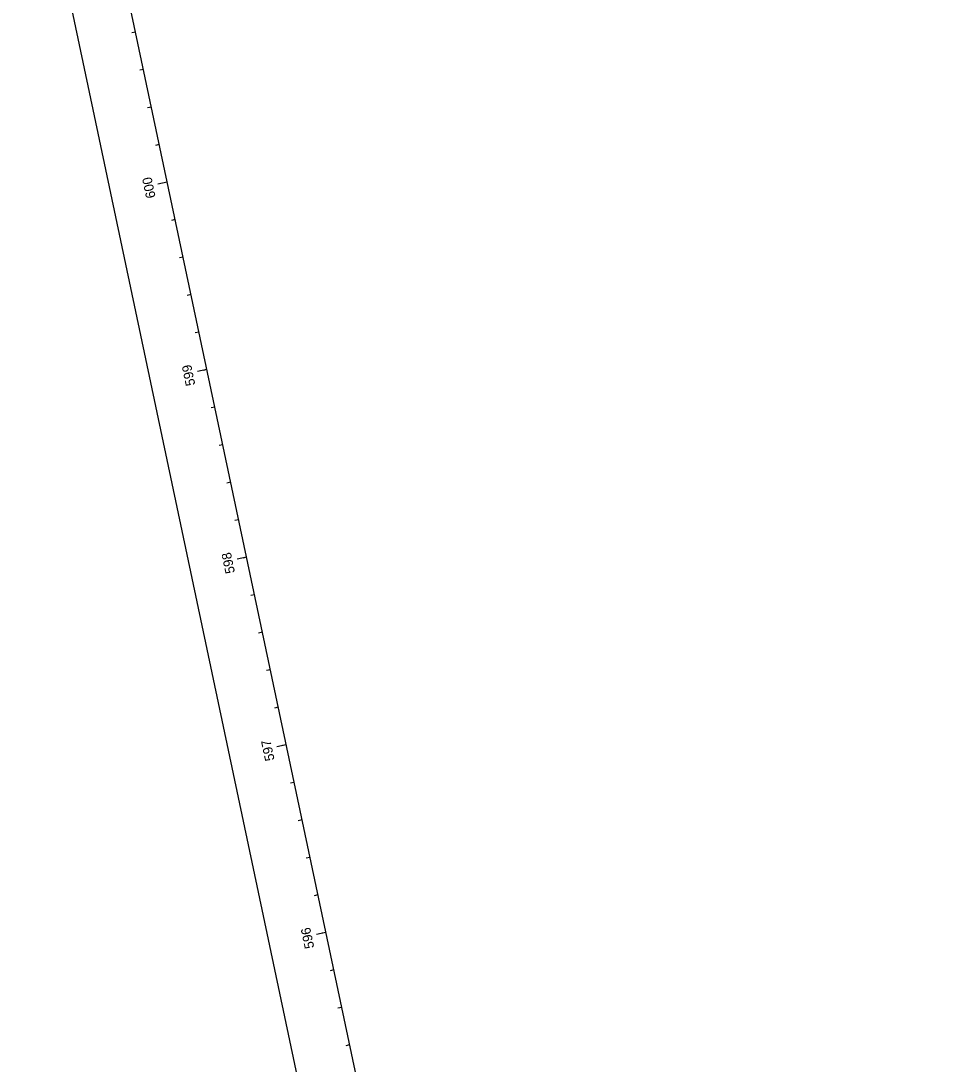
# Model space of a CAD drawing. Extents: x 2003883 to 2007688, y 399149 to 412300.
# Drawn here: x 2005065 to 2005555, y 406834 to 407378 of the extents above; entities that cross this region are included whole.
import ezdxf

# ---------------------------------------------------------------- set-up
doc = ezdxf.new("R2010")
doc.units = 0
for name, color, linetype in [('BaselineSurvey', 7, 'Continuous'), ('BaselineTextWt2', 7, 'Continuous'), ('DataBoxWt2', 7, 'Continuous'), ('Default', 7, 'Continuous'), ('EaseLine_ep', 7, 'Continuous'), ('PropertyLine_ep', 7, 'Continuous'), ('PropertyLineHook_ep', 7, 'Continuous'), ('PropertyLineSymbol_ep', 7, 'Continuous'), ('SubDivLineText', 7, 'Continuous'), ('SubLotNumberText', 7, 'Continuous'), ('SubVacOrigLotStaTie', 7, 'Continuous')]:
    doc.layers.add(name, color=color, linetype=linetype)

msp = doc.modelspace()

# ---------------------------------------------------------------- linework, layer by layer
at = {"layer": 'DataBoxWt2'}
for p, q in [((2005141.48, 407293.74), (2005136.59, 407292.71)), ((2005182.86, 407098.07), (2005180.9, 407097.66)), ((2005224.23, 406902.4), (2005222.27, 406901.98))]:
    msp.add_line(p, q, dxfattribs=at)
at = {"layer": 'Default'}
msp.add_line((2006223.92, 402174.38), (2005094.48, 407516.05), dxfattribs=at)
at = {"layer": 'EaseLine_ep'}
msp.add_line((2006194.57, 402168.18), (2005065.13, 407509.84), dxfattribs=at)
at = {"layer": 'PropertyLine_ep'}
msp.add_line((2006223.92, 402174.38), (2005094.48, 407516.05), dxfattribs=at)
at = {"layer": 'PropertyLineHook_ep'}
for p, q in [((2005124.93, 407372.01), (2005122.98, 407371.6)), ((2005129.07, 407352.45), (2005127.11, 407352.03)), ((2005133.21, 407332.88), (2005131.25, 407332.46)), ((2005137.35, 407313.31), (2005135.39, 407312.9)), ((2005141.48, 407293.74), (2005136.59, 407292.71)), ((2005145.62, 407274.18), (2005143.66, 407273.76)), ((2005149.76, 407254.61), (2005147.8, 407254.2)), ((2005153.89, 407235.04), (2005151.94, 407234.63)), ((2005158.03, 407215.47), (2005156.08, 407215.06)), ((2005162.17, 407195.91), (2005157.28, 407194.87)), ((2005166.31, 407176.34), (2005164.35, 407175.93)), ((2005170.44, 407156.77), (2005168.49, 407156.36)), ((2005174.58, 407137.2), (2005172.62, 407136.79)), ((2005178.72, 407117.64), (2005176.76, 407117.22)), ((2005182.86, 407098.07), (2005177.96, 407097.04)), ((2005186.99, 407078.5), (2005185.04, 407078.09)), ((2005191.13, 407058.93), (2005189.17, 407058.52)), ((2005195.27, 407039.37), (2005193.31, 407038.95)), ((2005199.41, 407019.8), (2005197.45, 407019.39)), ((2005203.54, 407000.23), (2005198.65, 406999.2)), ((2005207.68, 406980.67), (2005205.72, 406980.25)), ((2005211.82, 406961.1), (2005209.86, 406960.68)), ((2005215.95, 406941.53), (2005214, 406941.12)), ((2005220.09, 406921.96), (2005218.14, 406921.55)), ((2005224.23, 406902.4), (2005219.34, 406901.36)), ((2005228.37, 406882.83), (2005226.41, 406882.41)), ((2005232.5, 406863.26), (2005230.55, 406862.85)), ((2005236.64, 406843.69), (2005234.68, 406843.28))]:
    msp.add_line(p, q, dxfattribs=at)
at = {"layer": 'SubDivLineText'}
for p, q in [((2005141.48, 407293.74), (2005136.59, 407292.71)), ((2005162.17, 407195.91), (2005160.21, 407195.49)), ((2005182.86, 407098.07), (2005180.9, 407097.66)), ((2005203.54, 407000.23), (2005201.59, 406999.82)), ((2005224.23, 406902.4), (2005222.27, 406901.98))]:
    msp.add_line(p, q, dxfattribs=at)
at = {"layer": 'SubVacOrigLotStaTie'}
msp.add_line((2005141.48, 407293.74), (2005136.59, 407292.71), dxfattribs=at)

# ---------------------------------------------------------------- texts
at = {"layer": 'BaselineSurvey'}
msp.add_text('600', height=4.98, rotation=101.9388, dxfattribs=at).set_placement((2005135.49, 407285.84))
at = {"layer": 'BaselineTextWt2'}
msp.add_text('600', height=4.98, rotation=101.9388, dxfattribs=at).set_placement((2005135.49, 407285.84))
at = {"layer": 'PropertyLineSymbol_ep'}
for s, p in [('600', (2005135.49, 407285.84)), ('599', (2005156.18, 407187.99)), ('598', (2005176.87, 407090.11)), ('597', (2005197.54, 406992.37)), ('596', (2005218.24, 406894.48))]:
    msp.add_text(s, height=4.98, rotation=101.9388, dxfattribs=at).set_placement(p)
at = {"layer": 'SubLotNumberText'}
msp.add_text('600', height=4.98, rotation=101.9388, dxfattribs=at).set_placement((2005135.49, 407285.84))

doc.saveas('drawing.dxf')
